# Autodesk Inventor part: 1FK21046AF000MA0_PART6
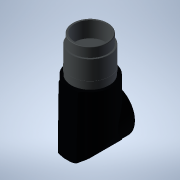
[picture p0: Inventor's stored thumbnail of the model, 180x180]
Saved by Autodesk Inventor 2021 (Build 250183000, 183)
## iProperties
Created: 2025-04
Part Number: 1FK21046AF000MA0_PART6
Material: Generic
Catalog Web Link: www.3dfindit.com
Description: -Servo synchronous motor
Document SubType Name: Modeling
Designer: psAdmin
Mass: 11.0817 g
Surface Area: 35.706 cm^2
Volume: 11.0817 cm^3
Density: 1 g/cm^3
Appearance: PSOLRGB-176-176-176
Category: PARTsolutions
Title: 1FK21046AF000MA0_PART6
Author: Cadenas PARTsolutions
Comments: Servo synchronous motor
Sending System: PARTsolutions
Preprocessor: ST-DEVELOPER v19.3
PSOL_IDENT_0: {$CADENAS_DATA/23d-libs/siemens_ag/_cat_/1c/1f/1fk21046af000ma0.prj},213 {VTYP=3D},{NB=1FK21046AF000
PSOL_IDENT_1: MA0_PART6},{LINA=1FK21046AF000MA0_PART6},{NN=1FK21046AF000MA0_PART6},{NOPRJ=TRUE},{DATE=19.08.2025 1
PSOL_IDENT_2: 4:00:28},{GEOMDATE=30.07.2025 02:02:08},{VERSION=},{LINEID=10},{WBVAR=},{WBNUMERIC=}  {NB=1FK21046AF
PSOL_IDENT_3: 000MA0_PART6},{LINA=1FK21046AF000MA0_PART6},{KT=DUMMY},{PREVIEW=../../../_pool_/cb/72/p_d211_xx_0043
PSOL_IDENT_4: 4j.png},{DESCSHORT=SIMOTICS S-1FK2 HD, SINAMICS S210 3AC 400V-480V, 3.2 Nm, 3000 rpm},{DESCLONG=SIMO
PSOL_IDENT_5: TICS S-1FK2 HD servo motor M0=3.2 Nm; PN = 1 kW at nN=3000 rpm (380-480 V); PN = 0.5 kW at nN=1500 r
PSOL_IDENT_6: pm (200-240 V); degree of protection IP64; cylindrical shaft D19x40mm; absolute encoder 22-bit + 12-
PSOL_IDENT_7: bit multiturn (encoder AM22DQC); with OCC interface; plug size M17, rotatable; SIMOTICS S-1FK2 servo
PSOL_IDENT_8: motorfor a wide range of uses in industrial environments. SIMOTICS S‑1FK2 servomotors are compact sy
PSOL_IDENT_9: nchronous motors with a high dynamic performance that set themselves apart as a result of their high
PSOL_IDENT_10: power density, degree of protection and overload capability. The motors are available in two varian
PSOL_IDENT_11: ts: as High Dynamic variant (highest dynamic performance as a result of the low intrinsic moment of
PSOL_IDENT_12: inertia for applications demanding a high dynamic performance with low moved masses) - and as Compac
PSOL_IDENT_13: t variant (precise and stable closed-loop control for medium up to large moved masses as a result of
PSOL_IDENT_14: a medium intrinsic moment of inertia). SIMOTICSS‑1FK2 servomotors fully exploit their strengths in
PSOL_IDENT_15: a system with the SINAMICSS210 frequency converter and simple connection using the one cable connect
PSOL_IDENT_16: ion (OCC). Advantages include the short control and positioning times, fast and precise correction o
PSOL_IDENT_17: f disturbing quantities as well as stable control with a high dynamic performance. The servo motors
PSOL_IDENT_18: can be configured to address a wide range of requirements. For example with and without holding brak
PSOL_IDENT_19: e, IP64 or IP65 degree of protection, singleturn or multiturn absolute encoders - to name just a few
PSOL_IDENT_20: . Further, the servomotors are available in different shaft heights extending from 20 to 100. A shaf
PSOL_IDENT_21: t sealing ring is available to achieve an IP65 degree of protection and for subsequent mounting at t
PSOL_IDENT_22: he motor or as spare part. SIMOTICS - the optimum motor for each and every motion control applicatio
PSOL_IDENT_23: n.},{INTNO=195125049666},{SUPPLIERALTNO=1FK2104-6AF00-0MA0},{MANUID=1FK21046AF000MA0},{MANUNAME=Siem
PSOL_IDENT_24: ens},{MANUTYPEDESC=Synchronous motor 1FK2-HD 3.2 NM},{AAU732=SIMOTICS},{AAO057=S-1FK2},{AAU734=SIMOT
PSOL_IDENT_25: ICS S-1FK2 HD servo motor M0=3.2 Nm; PN = 1 kW at nN=3000 rpm (380-480 V); PN = 0.5 kW at nN=1500 rp
PSOL_IDENT_26: m (200-240 V); degree of protection IP64; cylindrical shaft D19x40mm; absolute encoder 22-bit + 12-b
PSOL_IDENT_27: it multiturn (encoder AM22DQC); with OCC interface; plug size M17, rotatable;},{AAW338=Synchronous m
PSOL_IDENT_28: otor 1FK2-HD 3.2 NM},{AAO742=SIMOTICS},{AAO663=4042948694374},{NOCUPEROU=1},{PRICEQUANTITY=1},{QUANT
PSOL_IDENT_29: ITYMIN=1},{QUANTITYINT=1},{CTN=85015220},{COO=DE},{AAO676=1FK2104-6AF00-0MA0},{AAO677=Siemens AG},{O
PSOL_IDENT_30: RDERUNIT=C62},{CONTENTUNIT=C62}
NB: 1FK21046AF000MA0_PART6
NT: Servo synchronous motor
NBSYN: $MANUID._PART6
LINA: 1FK21046AF000MA0_PART6
CATALOG: SIEMENS
PREVIEW: ../../../_pool_/cb/72/p_d211_xx_00434j.png
DESCSHORT: SIMOTICS S-1FK2 HD, SINAMICS S210 3AC 400V-480V, 3.2 Nm, 3000 rpm
DESCLONG: SIMOTICS S-1FK2 HD servo motor M0=3.2 Nm; PN = 1 kW at nN=3000 rpm (380-480 V); PN = 0.5 kW at nN=1500 rpm (200-240 V); degree of protection IP64; cylindrical s
INTNO: 195125049666
SUPPLIERALTNO: 1FK2104-6AF00-0MA0
MANUID: 1FK21046AF000MA0
MANUNAME: Siemens
MANUTYPEDESC: Synchronous motor 1FK2-HD 3.2 NM
AAU732: SIMOTICS
AAO057: S-1FK2
AAU734: SIMOTICS S-1FK2 HD servo motor M0=3.2 Nm; PN = 1 kW at nN=3000 rpm (380-480 V); PN = 0.5 kW at nN=1500 rpm (200-240 V); degree of protection IP64; cylindrical s
AAW338: Synchronous motor 1FK2-HD 3.2 NM
AAO742: SIMOTICS
AAO663: 4042948694374.0
NOCUPEROU: 1
PRICEQUANTITY: 1
QUANTITYMIN: 1
QUANTITYINT: 1
CTN: 85015220
COO: DE
ARTICLENO: 1FK21046AF000MA0_PART6
BOMINFO: 1FK21046AF000MA0_PART6
CREATOR: CADENAS GmbH
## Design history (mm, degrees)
feature "2025_04_17_15_39_11_0378"
body "Solid1"
